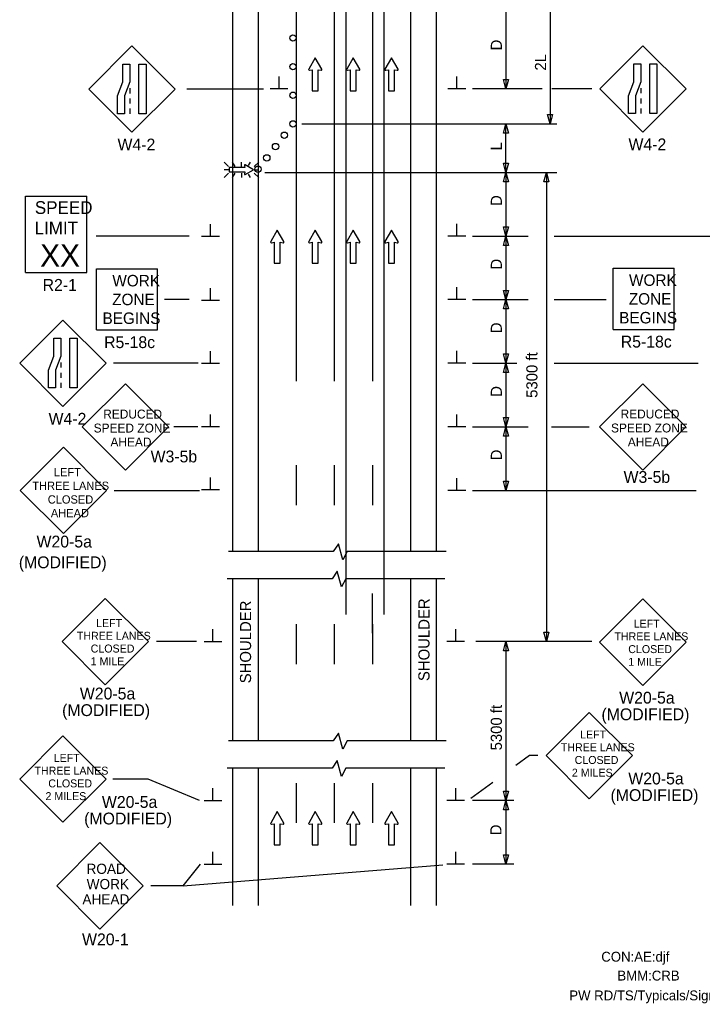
# Model space of a CAD drawing. Extents: x 16725 to 18475, y 5932 to 7023.
# Drawn here: x 16725 to 17154, y 5932 to 6551 of the extents above; entities that cross this region are included whole.
import ezdxf

# ---------------------------------------------------------------- set-up
doc = ezdxf.new("R2010")
doc.units = 0
for name, color, linetype in [('ALI_LEGAL_EX', 7, 'Continuous'), ('BORDER_SIGNAL_WO', 7, 'Continuous'), ('MT_SCRATCH_LEVEL_E', 7, 'Continuous'), ('PAVT_EDGE_EX', 7, 'Continuous'), ('TRAFFIC_SIGNS_PR', 7, 'Continuous'), ('TYPICAL_TEXT_DIMEN_PR', 7, 'Continuous')]:
    doc.layers.add(name, color=color, linetype=linetype)

msp = doc.modelspace()

# ---------------------------------------------------------------- linework, layer by layer
at = {"layer": 'ALI_LEGAL_EX'}
for p, q in [((16898.69, 7022.86), (16898.69, 6323.13)), ((16922.69, 7022.86), (16922.69, 6323.13)), ((16946.69, 7022.86), (16946.69, 6323.13)), ((16929.88, 7005.57), (16929.88, 6176.39)), ((16953.88, 7005.57), (16953.88, 6176.39)), ((16953.88, 7005.57), (16953.88, 6176.39))]:
    msp.add_line(p, q, dxfattribs=at)
for points in [[(16922.69, 6470.26), (16922.69, 6445.26)], [(16946.69, 6470.26), (16946.69, 6445.26)], [(16898.69, 6370.26), (16898.69, 6345.26)], [(16922.69, 6370.26), (16922.69, 6345.26)], [(16946.69, 6370.26), (16946.69, 6345.26)], [(16898.69, 6270.26), (16898.69, 6245.26)], [(16922.69, 6270.26), (16922.69, 6245.26)], [(16946.69, 6270.26), (16946.69, 6245.26)], [(16946.69, 6164.66), (16946.69, 6189.66)], [(16898.69, 6170.26), (16898.69, 6145.26)], [(16922.69, 6170.26), (16922.69, 6145.26)], [(16946.69, 6170.26), (16946.69, 6145.26)], [(16898.69, 6070.26), (16898.69, 6045.26)], [(16922.69, 6070.26), (16922.69, 6045.26)], [(16946.69, 6070.26), (16946.69, 6045.26)]]:
    msp.add_lwpolyline(points, dxfattribs=at)
at = {"layer": 'MT_SCRATCH_LEVEL_E'}
for p, q in [((16910.69, 6526.59), (16906.58, 6519.35)), ((16914.84, 6519.35), (16910.69, 6526.59)), ((16934.6, 6526.59), (16930.49, 6519.35)), ((16938.74, 6519.35), (16934.6, 6526.59)), ((16958.65, 6526.59), (16954.54, 6519.35)), ((16962.8, 6519.35), (16958.65, 6526.59)), ((16907.06, 6518.67), (16908.84, 6518.98)), ((16908.84, 6518.98), (16908.84, 6505.73)), ((16912.58, 6505.73), (16912.58, 6518.98)), ((16912.58, 6518.98), (16914.36, 6518.67)), ((16930.97, 6518.67), (16932.74, 6518.98)), ((16932.74, 6518.98), (16932.74, 6505.73)), ((16936.49, 6505.73), (16936.49, 6518.98)), ((16936.49, 6518.98), (16938.26, 6518.67)), ((16955.02, 6518.67), (16956.8, 6518.98)), ((16956.8, 6518.98), (16956.8, 6505.73)), ((16960.54, 6505.73), (16960.54, 6518.98)), ((16960.54, 6518.98), (16962.32, 6518.67)), ((16908.84, 6505.73), (16912.58, 6505.73)), ((16932.74, 6505.73), (16936.49, 6505.73)), ((16956.8, 6505.73), (16960.54, 6505.73)), ((16886.79, 6418.14), (16882.68, 6410.9)), ((16890.94, 6410.9), (16886.79, 6418.14)), ((16910.69, 6418.14), (16906.58, 6410.9)), ((16914.84, 6410.9), (16910.69, 6418.14)), ((16934.6, 6418.14), (16930.49, 6410.9)), ((16938.74, 6410.9), (16934.6, 6418.14)), ((16958.65, 6418.14), (16954.54, 6410.9)), ((16962.8, 6410.9), (16958.65, 6418.14)), ((16883.16, 6410.22), (16884.94, 6410.53)), ((16884.94, 6410.53), (16884.94, 6397.28)), ((16888.68, 6397.28), (16888.68, 6410.53)), ((16888.68, 6410.53), (16890.46, 6410.22)), ((16907.06, 6410.22), (16908.84, 6410.53)), ((16908.84, 6410.53), (16908.84, 6397.28)), ((16912.58, 6397.28), (16912.58, 6410.53)), ((16912.58, 6410.53), (16914.36, 6410.22)), ((16930.97, 6410.22), (16932.74, 6410.53)), ((16932.74, 6410.53), (16932.74, 6397.28)), ((16936.49, 6397.28), (16936.49, 6410.53)), ((16936.49, 6410.53), (16938.26, 6410.22)), ((16955.02, 6410.22), (16956.8, 6410.53)), ((16956.8, 6410.53), (16956.8, 6397.28)), ((16960.54, 6397.28), (16960.54, 6410.53)), ((16960.54, 6410.53), (16962.32, 6410.22)), ((16884.94, 6397.28), (16888.68, 6397.28)), ((16908.84, 6397.28), (16912.58, 6397.28)), ((16932.74, 6397.28), (16936.49, 6397.28)), ((16956.8, 6397.28), (16960.54, 6397.28)), ((16886.79, 6052.44), (16882.68, 6045.2)), ((16890.94, 6045.2), (16886.79, 6052.44)), ((16910.69, 6052.44), (16906.58, 6045.2)), ((16914.84, 6045.2), (16910.69, 6052.44)), ((16934.6, 6052.44), (16930.49, 6045.2)), ((16938.74, 6045.2), (16934.6, 6052.44)), ((16958.65, 6052.44), (16954.54, 6045.2)), ((16962.8, 6045.2), (16958.65, 6052.44)), ((16883.16, 6044.51), (16884.94, 6044.83)), ((16884.94, 6044.83), (16884.94, 6031.57)), ((16888.68, 6031.57), (16888.68, 6044.83)), ((16888.68, 6044.83), (16890.46, 6044.51)), ((16907.06, 6044.51), (16908.84, 6044.83)), ((16908.84, 6044.83), (16908.84, 6031.57)), ((16912.58, 6031.57), (16912.58, 6044.83)), ((16912.58, 6044.83), (16914.36, 6044.51)), ((16930.97, 6044.51), (16932.74, 6044.83)), ((16932.74, 6044.83), (16932.74, 6031.57)), ((16936.49, 6031.57), (16936.49, 6044.83)), ((16936.49, 6044.83), (16938.26, 6044.51)), ((16955.02, 6044.51), (16956.8, 6044.83)), ((16956.8, 6044.83), (16956.8, 6031.57)), ((16960.54, 6031.57), (16960.54, 6044.83)), ((16960.54, 6044.83), (16962.32, 6044.51)), ((16884.94, 6031.57), (16888.68, 6031.57)), ((16908.84, 6031.57), (16912.58, 6031.57)), ((16932.74, 6031.57), (16936.49, 6031.57)), ((16956.8, 6031.57), (16960.54, 6031.57))]:
    msp.add_line(p, q, dxfattribs=at)
for centre, start, end in [((16906.99, 6519.13), 150.42484, 279.96381), ((16914.43, 6519.13), 260.03619, 29.77312), ((16930.89, 6519.13), 150.42484, 279.96381), ((16938.33, 6519.13), 260.03619, 29.77312), ((16954.95, 6519.13), 150.42484, 279.96381), ((16962.39, 6519.13), 260.03619, 29.77312), ((16883.09, 6410.68), 150.42484, 279.96381), ((16890.53, 6410.68), 260.03619, 29.77312), ((16906.99, 6410.68), 150.42484, 279.96381), ((16914.43, 6410.68), 260.03619, 29.77312), ((16930.89, 6410.68), 150.42484, 279.96381), ((16938.33, 6410.68), 260.03619, 29.77312), ((16954.95, 6410.68), 150.42484, 279.96381), ((16962.39, 6410.68), 260.03619, 29.77312), ((16883.09, 6044.97), 150.42484, 279.96381), ((16890.53, 6044.97), 260.03619, 29.77312), ((16906.99, 6044.97), 150.42484, 279.96381), ((16914.43, 6044.97), 260.03619, 29.77312), ((16930.89, 6044.97), 150.42484, 279.96381), ((16938.33, 6044.97), 260.03619, 29.77312), ((16954.95, 6044.97), 150.42484, 279.96381), ((16962.39, 6044.97), 260.03619, 29.77312)]:
    msp.add_arc(centre, 0.463, start, end, dxfattribs=at)
at = {"layer": 'PAVT_EDGE_EX'}
for p, q in [((16858.69, 6927.61), (16858.69, 6215.97)), ((16874.69, 6927.61), (16874.69, 6215.97)), ((16970.69, 6927.61), (16970.69, 6215.97)), ((16986.69, 6927.61), (16986.69, 6215.97)), ((16858.69, 6199.33), (16858.69, 6096.88)), ((16874.69, 6198.84), (16874.69, 6096.88)), ((16970.69, 6198.84), (16970.69, 6096.88)), ((16986.69, 6198.84), (16986.69, 6096.88)), ((16858.69, 6079.74), (16858.69, 5993.28)), ((16874.69, 6079.74), (16874.69, 5993.28)), ((16970.69, 6079.74), (16970.69, 5993.28)), ((16986.69, 6079.74), (16986.69, 5993.28))]:
    msp.add_line(p, q, dxfattribs=at)
at = {"layer": 'TRAFFIC_SIGNS_PR'}
for p, q in [((16795.32, 6534), (16768.17, 6506.85)), ((16822.47, 6506.85), (16795.32, 6534)), ((17116.84, 6534.09), (17089.69, 6506.94)), ((17143.99, 6506.94), (17116.84, 6534.09)), ((16768.17, 6506.85), (16795.32, 6479.7)), ((16794.07, 6507.34), (16794.07, 6504.14)), ((16795.32, 6479.7), (16822.47, 6506.85)), ((17089.69, 6506.94), (17116.84, 6479.79)), ((17115.59, 6507.43), (17115.59, 6504.23)), ((17116.84, 6479.79), (17143.99, 6506.94)), ((16794.07, 6500.94), (16794.07, 6497.74)), ((17115.59, 6501.03), (17115.59, 6497.83)), ((16794.07, 6494.54), (16794.07, 6491.34)), ((17115.59, 6494.63), (17115.59, 6491.43)), ((16856.17, 6458.13), (16853.35, 6460.95)), ((16858.47, 6460.95), (16860.1, 6458.13)), ((16864.26, 6458.13), (16864.26, 6460.95)), ((16869.73, 6460.95), (16868.52, 6458.85)), ((16875.16, 6460.94), (16872.34, 6458.13)), ((16856.17, 6456.1), (16853.35, 6456.1)), ((16856.17, 6454.06), (16853.35, 6451.24)), ((16860.12, 6454.06), (16858.49, 6451.24)), ((16864.26, 6454.06), (16864.26, 6451.24)), ((16868.44, 6453.43), (16869.7, 6451.24)), ((16872.34, 6456.1), (16875.16, 6456.1)), ((16875.16, 6451.24), (16872.34, 6454.06)), ((16728.45, 6439.48), (16766.9, 6439.48)), ((16728.45, 6391.42), (16728.45, 6439.48)), ((16766.9, 6391.42), (16766.9, 6439.48)), ((16728.45, 6391.42), (16766.9, 6391.42)), ((16773.01, 6355.39), (16773.01, 6393.79)), ((16773.01, 6393.79), (16811.41, 6393.79)), ((16811.41, 6355.39), (16811.41, 6393.79)), ((17098.12, 6355.72), (17098.12, 6394.12)), ((17098.12, 6394.12), (17136.52, 6394.12)), ((17136.52, 6355.72), (17136.52, 6394.12)), ((16751.93, 6361.53), (16724.78, 6334.38)), ((16779.09, 6334.38), (16751.93, 6361.53)), ((16773.01, 6355.39), (16811.41, 6355.39)), ((17098.12, 6355.72), (17136.52, 6355.72)), ((16724.78, 6334.38), (16751.93, 6307.22)), ((16750.69, 6334.87), (16750.69, 6331.67)), ((16751.93, 6307.22), (16779.09, 6334.38)), ((16750.69, 6328.47), (16750.69, 6325.27)), ((16750.69, 6322.07), (16750.69, 6318.87)), ((16791.22, 6321.51), (16764.07, 6294.35)), ((16818.37, 6294.35), (16791.22, 6321.51)), ((17116.77, 6321.55), (17089.62, 6294.39)), ((17143.92, 6294.39), (17116.77, 6321.55)), ((16764.07, 6294.35), (16791.22, 6267.2)), ((16791.22, 6267.2), (16818.37, 6294.35)), ((17089.62, 6294.39), (17116.77, 6267.24)), ((17116.77, 6267.24), (17143.92, 6294.39)), ((16752.26, 6281.58), (16725.1, 6254.42)), ((16779.41, 6254.42), (16752.26, 6281.58)), ((16725.1, 6254.42), (16752.26, 6227.27)), ((16752.26, 6227.27), (16779.41, 6254.42)), ((16778.56, 6186.53), (16751.37, 6159.34)), ((16805.74, 6159.34), (16778.56, 6186.53)), ((17116.82, 6186.17), (17089.64, 6158.98)), ((17144.01, 6158.98), (17116.82, 6186.17)), ((16751.37, 6159.34), (16778.56, 6132.16)), ((16778.56, 6132.16), (16805.74, 6159.34)), ((17089.64, 6158.98), (17116.82, 6131.8)), ((17116.82, 6131.8), (17144.01, 6158.98)), ((17083.1, 6114.8), (17055.91, 6087.61)), ((17110.29, 6087.61), (17083.1, 6114.8)), ((16751.88, 6100.07), (16724.7, 6072.88)), ((16779.07, 6072.88), (16751.88, 6100.07)), ((17055.91, 6087.61), (17083.1, 6060.43)), ((17083.1, 6060.43), (17110.29, 6087.61)), ((16724.7, 6072.88), (16751.88, 6045.69)), ((16751.88, 6045.69), (16779.07, 6072.88)), ((16775.22, 6032.89), (16748.03, 6005.71)), ((16802.4, 6005.71), (16775.22, 6032.89)), ((16748.03, 6005.71), (16775.22, 5978.52)), ((16775.22, 5978.52), (16802.4, 6005.71))]:
    msp.add_line(p, q, dxfattribs=at)
for points in [[(16794.07, 6522.58), (16794.07, 6511.4), (16790.73, 6502.52), (16790.73, 6491.34), (16786.24, 6491.34), (16786.24, 6502.52), (16789.58, 6511.4), (16789.58, 6522.58)], [(16804.21, 6522.58), (16804.21, 6491.34), (16799.72, 6491.34), (16799.72, 6522.58)], [(17115.59, 6522.68), (17115.59, 6511.5), (17112.25, 6502.61), (17112.25, 6491.43), (17107.76, 6491.43), (17107.76, 6502.61), (17111.1, 6511.5), (17111.1, 6522.68)], [(17125.73, 6522.68), (17125.73, 6491.43), (17121.24, 6491.43), (17121.24, 6522.68)], [(16750.69, 6350.11), (16750.69, 6338.93), (16747.34, 6330.05), (16747.34, 6318.87), (16742.85, 6318.87), (16742.85, 6330.05), (16746.19, 6338.93), (16746.19, 6350.11)], [(16760.82, 6350.11), (16760.82, 6318.87), (16756.33, 6318.87), (16756.33, 6350.11)]]:
    msp.add_lwpolyline(points, close=True, dxfattribs=at)
for points in [[(16866.58, 6453.08), (16871.89, 6456.1), (16866.58, 6459.14)], [(16866.08, 6458.78), (16866.31, 6457.48), (16856.59, 6457.48), (16856.59, 6454.74), (16866.31, 6454.74), (16866.08, 6453.43)]]:
    msp.add_lwpolyline(points, dxfattribs=at)
for centre in [(16896.69, 6538.97), (16896.69, 6520.97), (16896.69, 6502.97), (16896.69, 6484.97), (16891.2, 6477.84), (16885.7, 6470.71), (16880.2, 6463.58), (16874.7, 6456.46)]:
    msp.add_circle(centre, 2, dxfattribs=at)
for centre, start, end in [((16866.42, 6458.84), 61.48329, 189.95933), ((16866.42, 6453.38), 170.73078, 298.89165)]:
    msp.add_arc(centre, 0.341, start, end, dxfattribs=at)
at = {"layer": 'TYPICAL_TEXT_DIMEN_PR'}
for p, q in [((17030.69, 6556.97), (17030.69, 6506.97)), ((17058.5, 6556.97), (17058.5, 6484.97)), ((16887.91, 6506.97), (16887.91, 6514.76)), ((16999.82, 6506.97), (16999.82, 6514.76)), ((17030.69, 6506.97), (17029.12, 6512.84)), ((17029.12, 6512.84), (17030.69, 6512.84)), ((17030.69, 6512.84), (17032.26, 6512.84)), ((17032.26, 6512.84), (17030.69, 6506.97)), ((17058.5, 6511.84), (17058.5, 6508.07)), ((16829.94, 6506.97), (16878.12, 6506.97)), ((16893.53, 6506.97), (16882.28, 6506.97)), ((17005.44, 6506.97), (16994.19, 6506.97)), ((17053.48, 6506.97), (17009.69, 6506.97)), ((17084.64, 6506.97), (17059.59, 6506.97)), ((17058.5, 6484.97), (17056.93, 6490.84)), ((17056.93, 6490.84), (17058.5, 6490.84)), ((17058.5, 6490.84), (17060.07, 6490.84)), ((17060.07, 6490.84), (17058.5, 6484.97)), ((16902.24, 6484.97), (17062.74, 6484.97)), ((17029.12, 6479.11), (17030.69, 6484.97)), ((17030.69, 6454.41), (17030.69, 6484.97)), ((17030.69, 6484.97), (17032.26, 6479.11)), ((17030.69, 6479.11), (17029.12, 6479.11)), ((17032.26, 6479.11), (17030.69, 6479.11)), ((17030.69, 6454.41), (17029.12, 6460.27)), ((17029.12, 6460.27), (17030.69, 6460.27)), ((17030.69, 6460.27), (17032.26, 6460.27)), ((17032.26, 6460.27), (17030.69, 6454.41)), ((16878.96, 6454.41), (17062.74, 6454.41)), ((17029.12, 6448.55), (17030.69, 6454.41)), ((17030.69, 6454.41), (17030.69, 6414.41)), ((17030.69, 6454.41), (17032.26, 6448.55)), ((17054.56, 6448.55), (17056.13, 6454.41)), ((17056.13, 6454.41), (17056.13, 6159.31)), ((17056.13, 6454.41), (17057.7, 6448.55)), ((17030.69, 6448.55), (17029.12, 6448.55)), ((17032.26, 6448.55), (17030.69, 6448.55)), ((17056.13, 6448.55), (17054.56, 6448.55)), ((17057.7, 6448.55), (17056.13, 6448.55)), ((16844.81, 6414.16), (16844.81, 6421.94)), ((16999.82, 6414.41), (16999.82, 6422.19)), ((17030.69, 6414.41), (17029.12, 6420.27)), ((17029.12, 6420.27), (17030.69, 6420.27)), ((17030.69, 6420.27), (17032.26, 6420.27)), ((17032.26, 6420.27), (17030.69, 6414.41)), ((16831.38, 6414.41), (16772.8, 6414.41)), ((16850.44, 6414.16), (16839.19, 6414.16)), ((17005.44, 6414.41), (16994.19, 6414.41)), ((17009.69, 6414.41), (17044.61, 6414.41)), ((17029.12, 6408.55), (17030.69, 6414.41)), ((17030.69, 6414.41), (17030.69, 6374.41)), ((17030.69, 6414.41), (17032.26, 6408.55)), ((17060.93, 6414.41), (17160.46, 6414.41)), ((17030.69, 6408.55), (17029.12, 6408.55)), ((17032.26, 6408.55), (17030.69, 6408.55)), ((16844.81, 6373.91), (16844.81, 6381.69)), ((16999.82, 6374.41), (16999.82, 6382.19)), ((17030.69, 6374.41), (17029.12, 6380.27)), ((17029.12, 6380.27), (17030.69, 6380.27)), ((17030.69, 6380.27), (17032.26, 6380.27)), ((17032.26, 6380.27), (17030.69, 6374.41)), ((16831.38, 6374.41), (16815.9, 6374.41)), ((16850.44, 6373.91), (16839.19, 6373.91)), ((17005.44, 6374.41), (16994.19, 6374.41)), ((17009.69, 6374.41), (17044.61, 6374.41)), ((17029.12, 6368.55), (17030.69, 6374.41)), ((17030.69, 6374.41), (17030.69, 6334.41)), ((17030.69, 6374.41), (17032.26, 6368.55)), ((17060.93, 6374.41), (17093.83, 6374.41)), ((17030.69, 6368.55), (17029.12, 6368.55)), ((17032.26, 6368.55), (17030.69, 6368.55)), ((16844.81, 6334.17), (16844.81, 6341.96)), ((16999.82, 6334.41), (16999.82, 6342.19)), ((17030.69, 6334.41), (17029.12, 6340.27)), ((17029.12, 6340.27), (17030.69, 6340.27)), ((17030.69, 6340.27), (17032.26, 6340.27)), ((17032.26, 6340.27), (17030.69, 6334.41)), ((16837.08, 6334.41), (16783.69, 6334.41)), ((16850.44, 6334.17), (16839.19, 6334.17)), ((17005.44, 6334.41), (16994.19, 6334.41)), ((17009.69, 6334.41), (17037.62, 6334.41)), ((17029.12, 6328.55), (17030.69, 6334.41)), ((17030.69, 6334.41), (17030.69, 6294.41)), ((17030.69, 6334.41), (17032.26, 6328.55)), ((17060.93, 6334.41), (17151.63, 6334.41)), ((17030.69, 6328.55), (17029.12, 6328.55)), ((17032.26, 6328.55), (17030.69, 6328.55)), ((16844.81, 6294.43), (16844.81, 6302.22)), ((16999.82, 6294.41), (16999.82, 6302.19)), ((17030.69, 6294.41), (17029.12, 6300.27)), ((17029.12, 6300.27), (17030.69, 6300.27)), ((17030.69, 6300.27), (17032.26, 6300.27)), ((17032.26, 6300.27), (17030.69, 6294.41)), ((16836.86, 6294.41), (16821.64, 6294.41)), ((16850.44, 6294.43), (16839.19, 6294.43)), ((17005.44, 6294.41), (16994.19, 6294.41)), ((17009.69, 6294.41), (17044.61, 6294.41)), ((17029.12, 6288.55), (17030.69, 6294.41)), ((17030.69, 6294.41), (17030.69, 6254.41)), ((17030.69, 6294.41), (17032.26, 6288.55)), ((17059.29, 6294.41), (17083.1, 6294.41)), ((17030.69, 6288.55), (17029.12, 6288.55)), ((17032.26, 6288.55), (17030.69, 6288.55)), ((16844.81, 6254.7), (16844.81, 6262.48)), ((16999.82, 6254.41), (16999.82, 6262.19)), ((17030.69, 6254.41), (17029.12, 6260.27)), ((17029.12, 6260.27), (17030.69, 6260.27)), ((17030.69, 6260.27), (17032.26, 6260.27)), ((17032.26, 6260.27), (17030.69, 6254.41)), ((16784.09, 6254.41), (16837.84, 6254.41)), ((16850.44, 6254.7), (16839.19, 6254.7)), ((17005.44, 6254.41), (16994.19, 6254.41)), ((17009.69, 6254.41), (17150.37, 6254.41)), ((16925.31, 6220.77), (16922.05, 6215.97)), ((16928.05, 6210.83), (16925.31, 6220.77)), ((16922.05, 6215.97), (16856.11, 6215.97)), ((16930.79, 6215.97), (16928.05, 6210.83)), ((16993.12, 6215.97), (16930.79, 6215.97)), ((16924.51, 6203.64), (16921.25, 6198.84)), ((16927.25, 6193.7), (16924.51, 6203.64)), ((16921.25, 6198.84), (16855.31, 6198.84)), ((16929.99, 6198.84), (16927.25, 6193.7)), ((16992.32, 6198.84), (16929.99, 6198.84)), ((16846.32, 6159.31), (16846.32, 6167.1)), ((16999.07, 6159.31), (16999.07, 6167.1)), ((17056.13, 6159.31), (17054.56, 6165.18)), ((17054.56, 6165.18), (17056.13, 6165.18)), ((17056.13, 6165.18), (17057.7, 6165.18)), ((17057.7, 6165.18), (17056.13, 6159.31)), ((16835.96, 6159.31), (16810.82, 6159.31)), ((16840.69, 6159.31), (16851.94, 6159.31)), ((17004.69, 6159.31), (16993.44, 6159.31)), ((17084.64, 6159.31), (17011.64, 6159.31)), ((17029.12, 6153.45), (17030.69, 6159.31)), ((17030.69, 6159.31), (17030.69, 6059.31)), ((17030.69, 6159.31), (17032.26, 6153.45)), ((17030.69, 6153.45), (17029.12, 6153.45)), ((17032.26, 6153.45), (17030.69, 6153.45)), ((16925.31, 6101.68), (16922.05, 6096.88)), ((16928.05, 6091.74), (16925.31, 6101.68)), ((16922.05, 6096.88), (16856.11, 6096.88)), ((16930.79, 6096.88), (16928.05, 6091.74)), ((16993.12, 6096.88), (16930.79, 6096.88)), ((16924.51, 6084.54), (16921.25, 6079.74)), ((16927.25, 6074.6), (16924.51, 6084.54)), ((17045.45, 6087.61), (17036.98, 6081.43)), ((17050.68, 6087.61), (17045.45, 6087.61)), ((16921.25, 6079.74), (16855.31, 6079.74)), ((16929.99, 6079.74), (16927.25, 6074.6)), ((16992.32, 6079.74), (16929.99, 6079.74)), ((16805.63, 6072.9), (16783.32, 6072.9)), ((16837.88, 6059.48), (16805.63, 6072.9)), ((17022.36, 6070.75), (17008.61, 6060.71)), ((16846.32, 6059.31), (16846.32, 6067.1)), ((16999.07, 6059.31), (16999.07, 6067.1)), ((17030.69, 6059.31), (17029.12, 6065.18)), ((17029.12, 6065.18), (17030.69, 6065.18)), ((17030.69, 6065.18), (17032.26, 6065.18)), ((17032.26, 6065.18), (17030.69, 6059.31)), ((16840.69, 6059.31), (16851.94, 6059.31)), ((17004.69, 6059.31), (16993.44, 6059.31)), ((17035.69, 6059.31), (17009.69, 6059.31)), ((17029.12, 6053.45), (17030.69, 6059.31)), ((17030.69, 6059.31), (17030.69, 6019.31)), ((17030.69, 6059.31), (17032.26, 6053.45)), ((17030.69, 6053.45), (17029.12, 6053.45)), ((17032.26, 6053.45), (17030.69, 6053.45)), ((16846.32, 6019.31), (16846.32, 6027.1)), ((16999.07, 6019.31), (16999.07, 6027.1)), ((17030.69, 6019.31), (17029.12, 6025.18)), ((17029.12, 6025.18), (17030.69, 6025.18)), ((17030.69, 6025.18), (17032.26, 6025.18)), ((17032.26, 6025.18), (17030.69, 6019.31)), ((16827.68, 6005.71), (16838.4, 6019.36)), ((16827.68, 6005.71), (16991.03, 6018.98)), ((16840.69, 6019.31), (16851.94, 6019.31)), ((17004.69, 6019.31), (16993.44, 6019.31)), ((17035.69, 6019.31), (17009.69, 6019.31)), ((16827.68, 6005.71), (16807.22, 6005.71))]:
    msp.add_line(p, q, dxfattribs=at)

# ---------------------------------------------------------------- texts
at = {"layer": 'BORDER_SIGNAL_WO'}
for s, p in [('CON:AE:djf  ', (17090.69, 5958.06)), ('BMM:CRB', (17100.81, 5946.17)), ('PW RD/TS/Typicals/Signs/MT FWY/M1890a.dgn      ', (17070.55, 5933.71))]:
    msp.add_text(s, height=6.2, dxfattribs=at).set_placement(p)
at = {"layer": 'TRAFFIC_SIGNS_PR'}
for s, height, p in [('W4-2', 7.44, (16786.28, 6468.26)), ('W4-2', 7.44, (17107.8, 6468.35)), ('SPEED', 8.01, (16734.23, 6428.33)), ('LIMIT', 8.01, (16734.07, 6415.51)), ('XX', 14.048, (16737.58, 6395.18)), ('R2-1', 7.449, (16739.14, 6379.96)), ('WORK', 7.217, (16783.01, 6382.76)), ('WORK', 7.217, (17108.12, 6383.09)), ('ZONE', 7.217, (17108, 6371.28)), ('ZONE', 7.217, (16782.9, 6370.95)), ('BEGINS', 7.217, (16776.82, 6359.14)), ('BEGINS', 7.217, (17101.93, 6359.47)), ('R5-18c', 7.44, (16777.83, 6343.95)), ('R5-18c', 7.44, (17102.93, 6344.28)), ('REDUCED', 5.6, (16777.28, 6299.66)), ('REDUCED', 5.6, (17102.83, 6299.7)), ('W4-2', 7.44, (16742.89, 6295.78)), ('SPEED ZONE', 5.6, (16771.27, 6290.86)), ('SPEED ZONE', 5.6, (17096.82, 6290.9)), ('AHEAD', 5.6, (16781.83, 6282.06)), ('AHEAD', 5.6, (17107.38, 6282.1)), ('W3-5b', 7.44, (16807.09, 6272.07)), ('LEFT', 5.2, (16746.2, 6263.36)), ('W3-5b', 7.44, (17104.72, 6259.18)), ('THREE LANES', 5.2, (16732.65, 6254.76)), ('CLOSED', 5.2, (16742.38, 6246.16)), ('AHEAD', 5.2, (16744.32, 6237.56)), ('W20-5a', 7.44, (16735.32, 6218.54)), ('(MODIFIED)', 7.44, (16724.17, 6205.5)), ('LEFT', 5.006, (16772.8, 6168.5)), ('LEFT', 5.006, (17111.07, 6168.14)), ('THREE LANES', 5.0062, (16760.68, 6160.49)), ('THREE LANES', 5.0062, (17098.95, 6160.13)), ('CLOSED', 5.006, (16769.38, 6152.48)), ('CLOSED', 5.006, (17107.65, 6152.12)), ('1 MILE', 5.006, (16769.37, 6144.47)), ('1 MILE', 5.006, (17107.64, 6144.11)), ('W20-5a', 7.449, (16762.56, 6122.96)), ('W20-5a', 7.449, (17101.95, 6120.35)), ('(MODIFIED)', 7.449, (16751.4, 6112.5)), ('(MODIFIED)', 7.449, (17090.79, 6109.9)), ('LEFT', 5.006, (17077.34, 6098.41)), ('THREE LANES', 5.0062, (17065.22, 6090.4)), ('LEFT', 5.006, (16746.12, 6083.68)), ('CLOSED', 5.006, (17073.92, 6082.4)), ('THREE LANES', 5.0062, (16734.01, 6075.67)), ('2 MILES', 5.006, (17072.17, 6074.39)), ('W20-5a', 7.449, (17107.66, 6069.52)), ('CLOSED', 5.006, (16742.71, 6067.66)), ('2 MILES', 5.006, (16740.95, 6059.65)), ('(MODIFIED)', 7.449, (17096.5, 6059.07)), ('W20-5a', 7.449, (16776.44, 6054.79)), ('(MODIFIED)', 7.449, (16765.28, 6044.34)), ('ROAD', 6.408, (16766.75, 6013.25)), ('WORK', 6.408, (16766.86, 6003.64)), ('AHEAD', 6.408, (16764.17, 5994.03)), ('W20-1', 7.449, (16763.94, 5968.34))]:
    msp.add_text(s, height=height, dxfattribs=at).set_placement(p)
at = {"layer": 'TYPICAL_TEXT_DIMEN_PR'}
for s, p in [('D', (17028.14, 6531.19)), ('2L', (17055.94, 6518.48)), ('L', (17028.14, 6468.27)), ('D', (17028.14, 6433.33)), ('D', (17028.14, 6393.33)), ('D', (17028.14, 6353.33)), ('5300 ft', (17050.5, 6312.65)), ('D', (17028.14, 6313.33)), ('D', (17028.14, 6273.33)), ('SHOULDER', (16870.32, 6133.12)), ('SHOULDER', (16982.59, 6134.53)), ('5300 ft', (17028.14, 6090.92)), ('D', (17027.85, 6037.52))]:
    msp.add_text(s, height=7, rotation=90, dxfattribs=at).set_placement(p)

doc.saveas('drawing.dxf')
